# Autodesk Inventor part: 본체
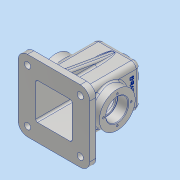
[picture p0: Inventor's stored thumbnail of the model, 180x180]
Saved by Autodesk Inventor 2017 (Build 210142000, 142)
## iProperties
Part Number: 본체
Material: 알루미늄 6061
Document SubType Name: Modeling
Designer: MRC
Density: 2.7 g/cm^3
Appearance: 알루미늄 - 평지
Mass: 753.626 g
Surface Area: 864.209 cm^2
Volume: 279.121 cm^3
Author: MRC
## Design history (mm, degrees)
sketch "스케치1"
  geometry: L1 (-34, 34)-(34, 34); L2 (34, 34)-(34, -34); L3 (34, -34)-(-34, -34); L4 (-34, -34)-(-34, 34); L5 (-34, 34)-(34, -34); L6 (34, 34)-(-34, -34); 1 further point
  constraints: 12 end point, 2 midpoint, 2 parallel, 1 horizontal, 1 perpendicular
  dimensions: "d0" = 68 distance of L2.end L3.end; "d1" = 68 distance of L3.end L1.start
extrude "돌출1" new body sketch "스케치1" distance "d2" = 53; taper "d4" = 0 deg; dims "d3" = 52, "d5" = 0
fillet "모깎기1" dims "d6" = 8
feature "쉘1" dims "d7" = 5
node "작업 평면2"
sketch "스케치3"
  geometry: C1 r 28.5 at (-26, 52); 1 further point
  constraints: 1 centre point, 1 coincident
  dimensions: "d10" = 57 diameter of C1
extrude "돌출2" join sketch "스케치3" stored distance "d11" = 53; taper "d12" = 0 deg
hole "구멍1" diameter "d15" = 30; stored, may be unused: countersink angle "d19" = 90 deg, drill point angle "d21" = 118 deg; dims "d13" = 10, "d14" = 10, "d16" = 6, "d17" = 35, "d18" = 17, "d20" = 8
sketch "스케치4"
  geometry: C1 r 17.5 at (0, 0) reference; 1 further point
  constraints: 1 vertical alignment
  dimensions: "d22" = 22 distance of point (0, 22) C1.centre
hole "구멍2" sketch "스케치4" at (0, 22) diameter "d23" = 3.242; stored, may be unused: countersink angle "d27" = 90 deg, drill point angle "d29" = 118 deg; dims "d24" = 8, "d25" = 35, "d26" = 17, "d28" = 10
sketch "스케치6"
  geometry: L1 (-26, -34)-(26, -34) reference; L2 (34, -26)-(34, 26) reference; L3 (26, 34)-(-26, 34) reference; L4 (-34, 26)-(-34, -26) reference; L5 (-57, -57)-(57, -57); L6 (57, -57)-(57, 57); L7 (57, 57)-(-57, 57); L8 (-57, 57)-(-57, -57); L9 (-57, -57)-(57, 57); L10 (57, -57)-(-57, 57); A1 r 8 centre (-26, -26) between (-34, -26) and (-26, -34) reference; A2 r 8 centre (26, -26) between (26, -34) and (34, -26) reference; A3 r 8 centre (26, 26) between (34, 26) and (26, 34) reference; A4 r 8 centre (-26, 26) between (-26, 34) and (-34, 26) reference; 1 further point
  constraints: 12 end point, 2 midpoint, 2 parallel, 1 horizontal, 1 perpendicular
  dimensions: "d34" = 114 distance of L7.end L6.end; "d35" = 114 distance of L5.end L6.end
extrude "돌출3" join sketch "스케치6" distance "d36" = 10; taper "d37" = 0 deg
fillet "모깎기2" dims "d38" = 15
sketch "스케치7"
  geometry: A1 r 15 centre (-42, 42) between (-42, 57) and (-57, 42) reference; A2 r 15 centre (42, 42) between (57, 42) and (42, 57) reference; 3 further points
  constraints: 2 coincident
  dimensions: "d39" = 84 distance of point (-42, 42) point (42, 42); "d40" = 42 horizontal distance of point (42, 42) point (0, 0) (= 0.5 x d39)
hole "구멍3" sketch "스케치7" at (42, 42), (-42, 42) diameter "d41" = 10; stored, may be unused: countersink angle "d45" = 90 deg, drill point angle "d47" = 118 deg; dims "d42" = 10, "d43" = 18, "d44" = 2, "d46" = 10
node "작업 평면3"
sketch "스케치8"
  geometry: C1 r 20 at (0, 0); 1 further point
  constraints: 1 centre point, 1 coincident
  dimensions: "d49" = 40 diameter of C1
extrude "돌출4" join sketch "스케치8" stored distance "d50" = 10; taper "d51" = 8 deg
hole "구멍4" diameter "d54" = 22.835; stored, may be unused: countersink angle "d58" = 90 deg, drill point angle "d60" = 118 deg; dims "d52" = 10, "d53" = 10, "d55" = 50, "d56" = 18, "d57" = 2, "d59" = 59.3
sketch "스케치9"
  geometry: L1 (-7, 42.829)-(-42, 49); L2 (-42, 57)-(-52, 57) reference; L3 (-42, 51)-(-42, 33) reference; 1 further point
  constraints: 2 end point, 1 point on line
  dimensions: "d61" = 10 deg angle of L2 L1; "d62" = 8 distance from line of L2 L1.end
feature "리브1" sketch "스케치9" dims "d63" = 1, "d64" = 10, "d65" = 0, "d66" = 0, "d67" = 1, "d68" = 1
fillet "모깎기3" dims "d69" = 3
fillet "모깎기4" dims "d70" = 3
chamfer "모따기1" distance "d71" = 1; stored, may be unused: second distance "d72" = 2, angle "d73" = 45 deg
sketch "스케치10"
  geometry: L1 (6, 18)-(46, 18) reference; L2 (-8, 0)-(0, 0) reference; 1 further point
  constraints: 1 other
  dimensions: "d74" = 25 distance from line of point (26, -7) L1; "d75" = 34 horizontal distance of point (26, -7) L2.start
feature "엠보싱1" sketch "스케치10" dims "d0" = 68, "d1" = 68, "d76" = 0.5, "d77" = 0
fillet "모깎기5" dims "d78" = 0.3
node "솔리드1"
pattern_circular "원형 패턴1" dims angle "d31" = 360 deg
mirror "미러1"
mirror "미러2"
mirror "미러3"
other parameters: "d9" = 15
